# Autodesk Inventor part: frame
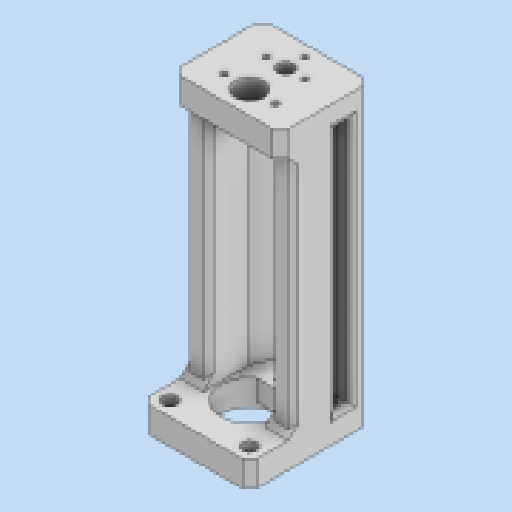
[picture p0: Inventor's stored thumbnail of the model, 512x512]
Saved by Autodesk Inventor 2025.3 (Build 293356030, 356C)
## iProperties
Created: 2025-12
Part Number: frame
Material: Generico
Document SubType Name: Modeling
Designer: Ryzen5700u
Density: 1 g/cm^3
Appearance: Default
Author: Ryzen5700u
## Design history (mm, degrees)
node "Piano di lavoro1"
sketch "Schizzo1"
  geometry: L1 (-0.604, 21)-(41.396, 21); L2 (41.396, 21)-(41.396, -21); L3 (41.396, -21)-(-0.604, -21); L4 (-0.604, -21)-(-0.604, 21); L5 (-0.604, 21)-(41.396, -21); L6 (41.396, 21)-(-0.604, -21); L7 (20.396, 0)-(20.396, -21); L8 (9.346, 0)-(9.346, 21); L9 (31.446, 0)-(31.446, 21); L10 (17.904, -15.759)-(11.328, -6.314); L11 (22.87, -15.784)-(29.464, -6.314); L12 (13.985, -9)-(26.807, -9); C1 r 1.8 at (20.396, 0) reference; C2 r 1.25 at (4.896, 15.5) reference; C3 r 1.25 at (35.896, 15.5) reference; C4 r 1.25 at (4.896, -15.5) reference; C5 r 1.25 at (35.896, -15.5) reference; C6 r 3.05 at (20.396, -14); C7 r 8 at (20.396, 0); A1 r 11.05 centre (20.396, 0) between (9.346, 0) and (31.446, 0); 5 further points
  constraints: 24 end point, 6 point on circle, 6 tangent, 3 centre point, 3 midpoint, 3 perpendicular, 3 point on line, 2 coincident, 2 horizontal, 2 parallel
  dimensions: "d0" = 42 distance of L2.end L3.end; "d1" = 42 distance of L1.end L2.end; "d2" = 22.1 diameter of A1; "d3" = 6.1 diameter of C6; "d4" = 14 distance of C1.centre C6.centre; "d7" = 16 diameter of C7; "d8" = 12 distance between parallel lines of L3 L12
extrude "Estrusione1" new body sketch "Schizzo1" distance "d5" = 10; taper "d6" = 0 deg
sketch "Schizzo2"
  geometry: C1 r 3.05 at (20.396, -14) reference; C2 r 2.258 at (20.396, -14); C3 r 1 at (20.396, -14); 1 further point
  constraints: 2 centre point, 2 coincident
  dimensions: "d9" = 2 diameter of C3
extrude "Estrusione2" join sketch "Schizzo2" distance "d10" = 7; taper "d11" = 0 deg
sketch "Schizzo3"
  geometry: C1 r 3.05 at (20.396, -14) reference; C2 r 1.6 at (20.396, -14); 1 further point
  constraints: 1 centre point, 1 coincident
  dimensions: "d12" = 3.2 diameter of C2
extrude "Estrusione3" join sketch "Schizzo3" distance "d13" = 7; taper "d14" = 0 deg
sketch "Schizzo4"
  geometry: L1 (26.807, 9)-(13.985, 9) reference; L2 (41.396, -21)-(-0.604, -21) reference; L3 (41.396, 21)-(41.396, -21) reference; L4 (-0.604, 21)-(41.396, 21) reference; L5 (-0.604, -21)-(-0.604, 21) reference; L6 (14.396, 16)-(14.396, 10) reference; L7 (14.396, 10)-(12.396, 10) reference; L8 (10.396, 8)-(10.396, -10) reference; L9 (10.396, -10)-(30.396, -10) reference; L10 (30.396, -10)-(30.396, 8) reference; L11 (28.396, 10)-(26.396, 10) reference; L12 (26.396, 10)-(26.396, 16) reference; L13 (41.396, -4)-(-0.604, -4); L14 (32.396, 12)-(8.396, 12); L15 (8.396, 12)-(8.396, -12); L16 (8.396, -12)-(32.396, -12); L17 (32.396, -12)-(32.396, 12); L18 (32.396, 12)-(8.396, -12); L19 (8.396, 12)-(32.396, -12); L20 (20.396, 14)-(20.396, 19); L21 (20.396, 19)-(11.396, 19); L22 (11.396, 19)-(8.396, 12); L23 (20.396, 19)-(29.396, 19); L24 (29.396, 19)-(32.396, 12); C1 r 1.25 at (4.896, -15.5) reference; C2 r 1.25 at (35.896, -15.5) reference; C3 r 1.25 at (4.896, 15.5) reference; C4 r 1.25 at (35.896, 15.5) reference; C5 r 2.25 at (20.396, 0) reference; C6 r 1.23 at (20.396, 6.5) reference; C7 r 1.23 at (14.767, -3.25) reference; C8 r 1.23 at (26.025, -3.25) reference; C9 r 3.05 at (20.396, 14) reference; C10 r 9.8 at (20.396, 0) reference; C11 r 1.6 at (20.396, 14) reference; A1 r 11.05 centre (20.396, 0) between (13.985, 9) and (26.807, 9) reference; A2 r 2 centre (28.396, 8) between (30.396, 8) and (28.396, 10) reference; A3 r 2 centre (24.396, 16) between (26.396, 16) and (24.396, 18) reference; A4 r 2 centre (16.396, 16) between (16.396, 18) and (14.396, 16) reference; A5 r 2 centre (12.396, 8) between (12.396, 10) and (10.396, 8) reference; 11 further points
  constraints: 24 end point, 3 perpendicular, 3 point on line, 2 midpoint, 2 parallel, 1 horizontal, 1 vertical
  dimensions: "d18" = 25 distance between parallel lines of L4 L13; "d39" = 24 distance of L16.end L15.end; "d40" = 24 distance of L15.end L14.end; "d42" = 5 distance of L20.start L20.end; "d43" = 9 distance of L20.end L21.end; "d44" = 9 distance of L20.end L23.end
extrude "Estrusione4" join sketch "Schizzo4" distance "d15" = 95; taper "d16" = 0 deg
sketch "Schizzo5"
  geometry: L1 (-0.604, 21)-(41.396, 21) reference; L2 (-0.604, -21)-(-0.604, 21) reference; L3 (41.396, 21)-(-0.604, 21); L4 (-0.604, 21)-(-0.604, -21); L5 (-0.604, -21)-(41.396, -21); L6 (41.396, -21)-(41.396, 21); L7 (-0.604, -4)-(41.396, -4) reference; L8 (41.396, -4)-(-0.604, -4); L9 (41.396, -9)-(-0.604, -9); C1 r 1.6 at (20.396, 14) reference; C2 r 3.05 at (20.396, 14); 6 further points
  constraints: 12 end point, 3 perpendicular, 3 point on line, 2 parallel, 1 centre point, 1 coincident, 1 horizontal, 1 midpoint
  dimensions: "d19" = 6.1 diameter of C2; "d22" = 5 distance from line of L8 point (20.396, -9)
extrude "Estrusione5" join sketch "Schizzo5" distance "d20" = 10; taper "d21" = 0 deg
sketch "Schizzo6"
  geometry: C1 r 2.25 at (20.396, 0) reference; 1 further point
hole "Foro1" sketch "Schizzo6" at (20.396, 0) diameter "d23" = 11.1; stored, may be unused: countersink angle "d27" = 90 deg, drill point angle "d29" = 118 deg; dims "d24" = 8, "d25" = 4, "d26" = 2, "d28" = 11.8
chamfer "Smusso1" distance "d30" = 2; stored, may be unused: second distance "d31" = 2, angle "d32" = 45 deg
chamfer "Smusso2" distance "d33" = 3; stored, may be unused: second distance "d34" = 2, angle "d35" = 45 deg
sketch "Schizzo7"
  geometry: C1 r 4 at (20.396, 0); 4 further points
  constraints: 1 centre point, 1 coincident, 1 other
  dimensions: "d36" = 8 diameter of C1
extrude "Estrusione6" join sketch "Schizzo7" distance "d37" = 3; taper "d38" = 0 deg
sketch "Schizzo8"
  geometry: L1 (0, 115)-(0, 0) reference; L2 (42, 0)-(0, 0) reference; L3 (42, 115)-(42, 0) reference; L4 (0, 115)-(42, 115) reference; 1 further point
extrude "Estrusione7" join sketch "Schizzo8" distance "d45" = 5; taper "d46" = 0 deg
chamfer "Smusso3" distance "d47" = 3; stored, may be unused: second distance "d48" = 2, angle "d49" = 45 deg
sketch "Schizzo9"
  geometry: L1 (35.896, 12.5)-(41.465, 12.5); L2 (35.896, 18.5)-(41.465, 18.5); L3 (4.896, 12.5)-(-0.604, 12.5); L4 (-0.604, -18)-(-0.604, 23) reference; L5 (4.896, 18.5)-(-0.604, 18.5); L6 (41.396, -18)-(41.396, 23) reference; L7 (41.396, 7.5)-(32.896, 7.5); L8 (32.896, 7.5)-(32.896, 15.5); L9 (32.896, 15.5)-(41.396, 15.5); L10 (41.396, 15.5)-(41.396, 7.5); L11 (-0.604, 7.5)-(7.896, 7.5); L12 (7.896, 7.5)-(7.896, 15.5); L13 (7.896, 15.5)-(-0.604, 15.5); L14 (-0.604, 15.5)-(-0.604, 7.5); C1 r 1.25 at (35.896, 15.5) reference; C2 r 1.25 at (4.896, 15.5) reference; A1 r 3 centre (35.896, 15.5) between (35.896, 12.5) and (35.896, 18.5); A2 r 3 centre (4.896, 15.5) between (4.896, 12.5) and (4.896, 18.5); 3 further points
  constraints: 24 end point, 6 point on circle, 5 horizontal, 4 parallel, 4 point on line, 3 perpendicular, 3 tangent, 2 centre point, 2 coincident
  dimensions: "d50" = 6 diameter of A1; "d51" = 6 diameter of A2; "d106" = 8 distance from line of C1.centre L7
extrude "Estrusione8" cut sketch "Schizzo9" distance "d52" = 25; taper "d53" = 0 deg
sketch "Schizzo10"
  geometry: C1 r 1.25 at (4.896, 15.5) reference; 2 further points
  constraints: 1 coincident
hole "Foro2" sketch "Schizzo10" at (4.896, 15.5) diameter "d54" = 3.4; stored, may be unused: countersink angle "d58" = 82 deg, drill point angle "d60" = 118 deg; dims "d55" = 6, "d56" = 5.5, "d57" = 3.4, "d59" = 11.8
sketch "Schizzo11"
  geometry: C1 r 1.25 at (35.896, 15.5) reference; 2 further points
  constraints: 1 coincident
hole "Foro3" sketch "Schizzo11" at (35.896, 15.5) diameter "d61" = 3.4; stored, may be unused: countersink angle "d65" = 90 deg, drill point angle "d67" = 118 deg; dims "d62" = 6, "d63" = 5.5, "d64" = 3.4, "d66" = 11.8
sketch "Schizzo12"
  geometry: L1 (15.896, -9.5)-(24.896, -9.5); L2 (24.896, -9.5)-(24.896, -18.5); L3 (24.896, -18.5)-(15.896, -18.5); L4 (15.896, -18.5)-(15.896, -9.5); L5 (15.896, -9.5)-(24.896, -18.5); L6 (24.896, -9.5)-(15.896, -18.5); L7 (2.396, -26)-(38.396, -26) reference; L8 (15.896, -18.5)-(24.896, -18.5); L9 (24.896, -18.5)-(24.896, -26); L10 (24.896, -26)-(15.896, -26); L11 (15.896, -26)-(15.896, -18.5); C1 r 3.05 at (20.396, -14) reference; C2 r 3.05 at (20.396, -14); 3 further points
  constraints: 20 end point, 4 parallel, 2 horizontal, 2 midpoint, 2 perpendicular, 1 centre point, 1 coincident, 1 point on line
  dimensions: "d69" = 9 distance of L2.end L3.end; "d70" = 9 distance of L1.end L2.end
extrude "Estrusione9" join sketch "Schizzo12" distance "d71" = 4; taper "d72" = 0 deg
sketch "Schizzo13"
  geometry: C1 r 1.25 at (35.896, -15.5) reference; C2 r 1.25 at (4.896, -15.5) reference; 3 further points
  constraints: 2 coincident
hole "Foro4" sketch "Schizzo13" at (35.896, -15.5), (4.896, -15.5) diameter "d73" = 3.4; stored, may be unused: countersink angle "d77" = 90 deg, drill point angle "d79" = 118 deg; dims "d74" = 6, "d75" = 5.6, "d76" = 3.4, "d78" = 11.8
sketch "Schizzo14"
  geometry: C1 r 1.6 at (20.396, -14) reference; 2 further points
  constraints: 1 coincident
hole "Foro5" sketch "Schizzo14" at (20.396, -14) diameter "d80" = 4.5; stored, may be unused: countersink angle "d84" = 90 deg, drill point angle "d86" = 118 deg; dims "d81" = 6, "d82" = 7, "d83" = 4, "d85" = 11.8
sketch "Schizzo15"
  geometry: L1 (20.396, 14)-(12.896, 14); L2 (15.896, 19)-(15.896, 9.5) reference; L3 (20.396, 14)-(27.896, 14); L4 (20.396, 14)-(20.396, 21.5); C1 r 2.25 at (20.396, 14) reference; C2 r 3.5 at (20.396, 14) reference; C3 r 3.05 at (20.396, 14) reference; C4 r 5.55 at (20.396, 0) reference; A1 r 7.5 centre (20.396, 14) between (12.896, 14) and (27.896, 14); A2 r 10 centre (20.396, 0) between (30.396, 0) and (10.396, 0); 1 further point
  constraints: 6 end point, 5 point on circle, 2 centre point, 2 coincident, 1 horizontal, 1 perpendicular, 1 vertical
  dimensions: "d87" = 15 diameter of A1; "d105" = 20 diameter of A2
hole "Foro6" sketch "Schizzo15" at (20.396, 21.5), (27.896, 14), (12.896, 14), (30.396, 0), (10.396, 0) diameter "d88" = 2.4; stored, may be unused: countersink angle "d92" = 82 deg, drill point angle "d94" = 118 deg; dims "d89" = 12, "d90" = 3.023, "d91" = 2, "d93" = 8
chamfer "Smusso4" distance "d95" = 2; stored, may be unused: second distance "d96" = 2, angle "d97" = 45 deg
sketch "Schizzo16"
  geometry: C1 r 11.05 at (20.396, 0); A1 r 11.05 centre (20.396, 0) between (26.807, -9) and (13.985, -9) reference; 3 further points
  constraints: 1 centre point, 1 coincident
  dimensions: "d98" = 22.1 diameter of C1
extrude "Estrusione10" cut sketch "Schizzo16" distance "d99" = 2; taper "d100" = 0 deg
sketch "Schizzo17"
  geometry: C1 r 11.05 at (20.396, 0); C2 r 3.5 at (20.396, -14) reference; C3 r 3.5 at (20.396, -14); A1 r 11.05 centre (20.396, 0) between (26.807, -9) and (13.985, -9) reference; 3 further points
  constraints: 2 centre point, 2 coincident
extrude "Estrusione11" join sketch "Schizzo17" stored distance "d101" = 10; taper "d102" = 0 deg
sketch "Schizzo19"
  geometry: C1 r 3.05 at (20.396, 14) reference; 1 further point
extrude "Estrusione12" cut sketch "Schizzo19" distance "d103" = 6; taper "d104" = 0 deg
fillet "Raccordo2" dims "d107" = 5
node "Solido1"
node "Riferimento1"
node "Riferimento2"
node "Riferimento3"
node "Riferimento4"
node "Riferimento5"
node "Linea chiusa proiettata1"
node "Riferimento7"
node "Riferimento8"
node "Linea chiusa proiettata2"
